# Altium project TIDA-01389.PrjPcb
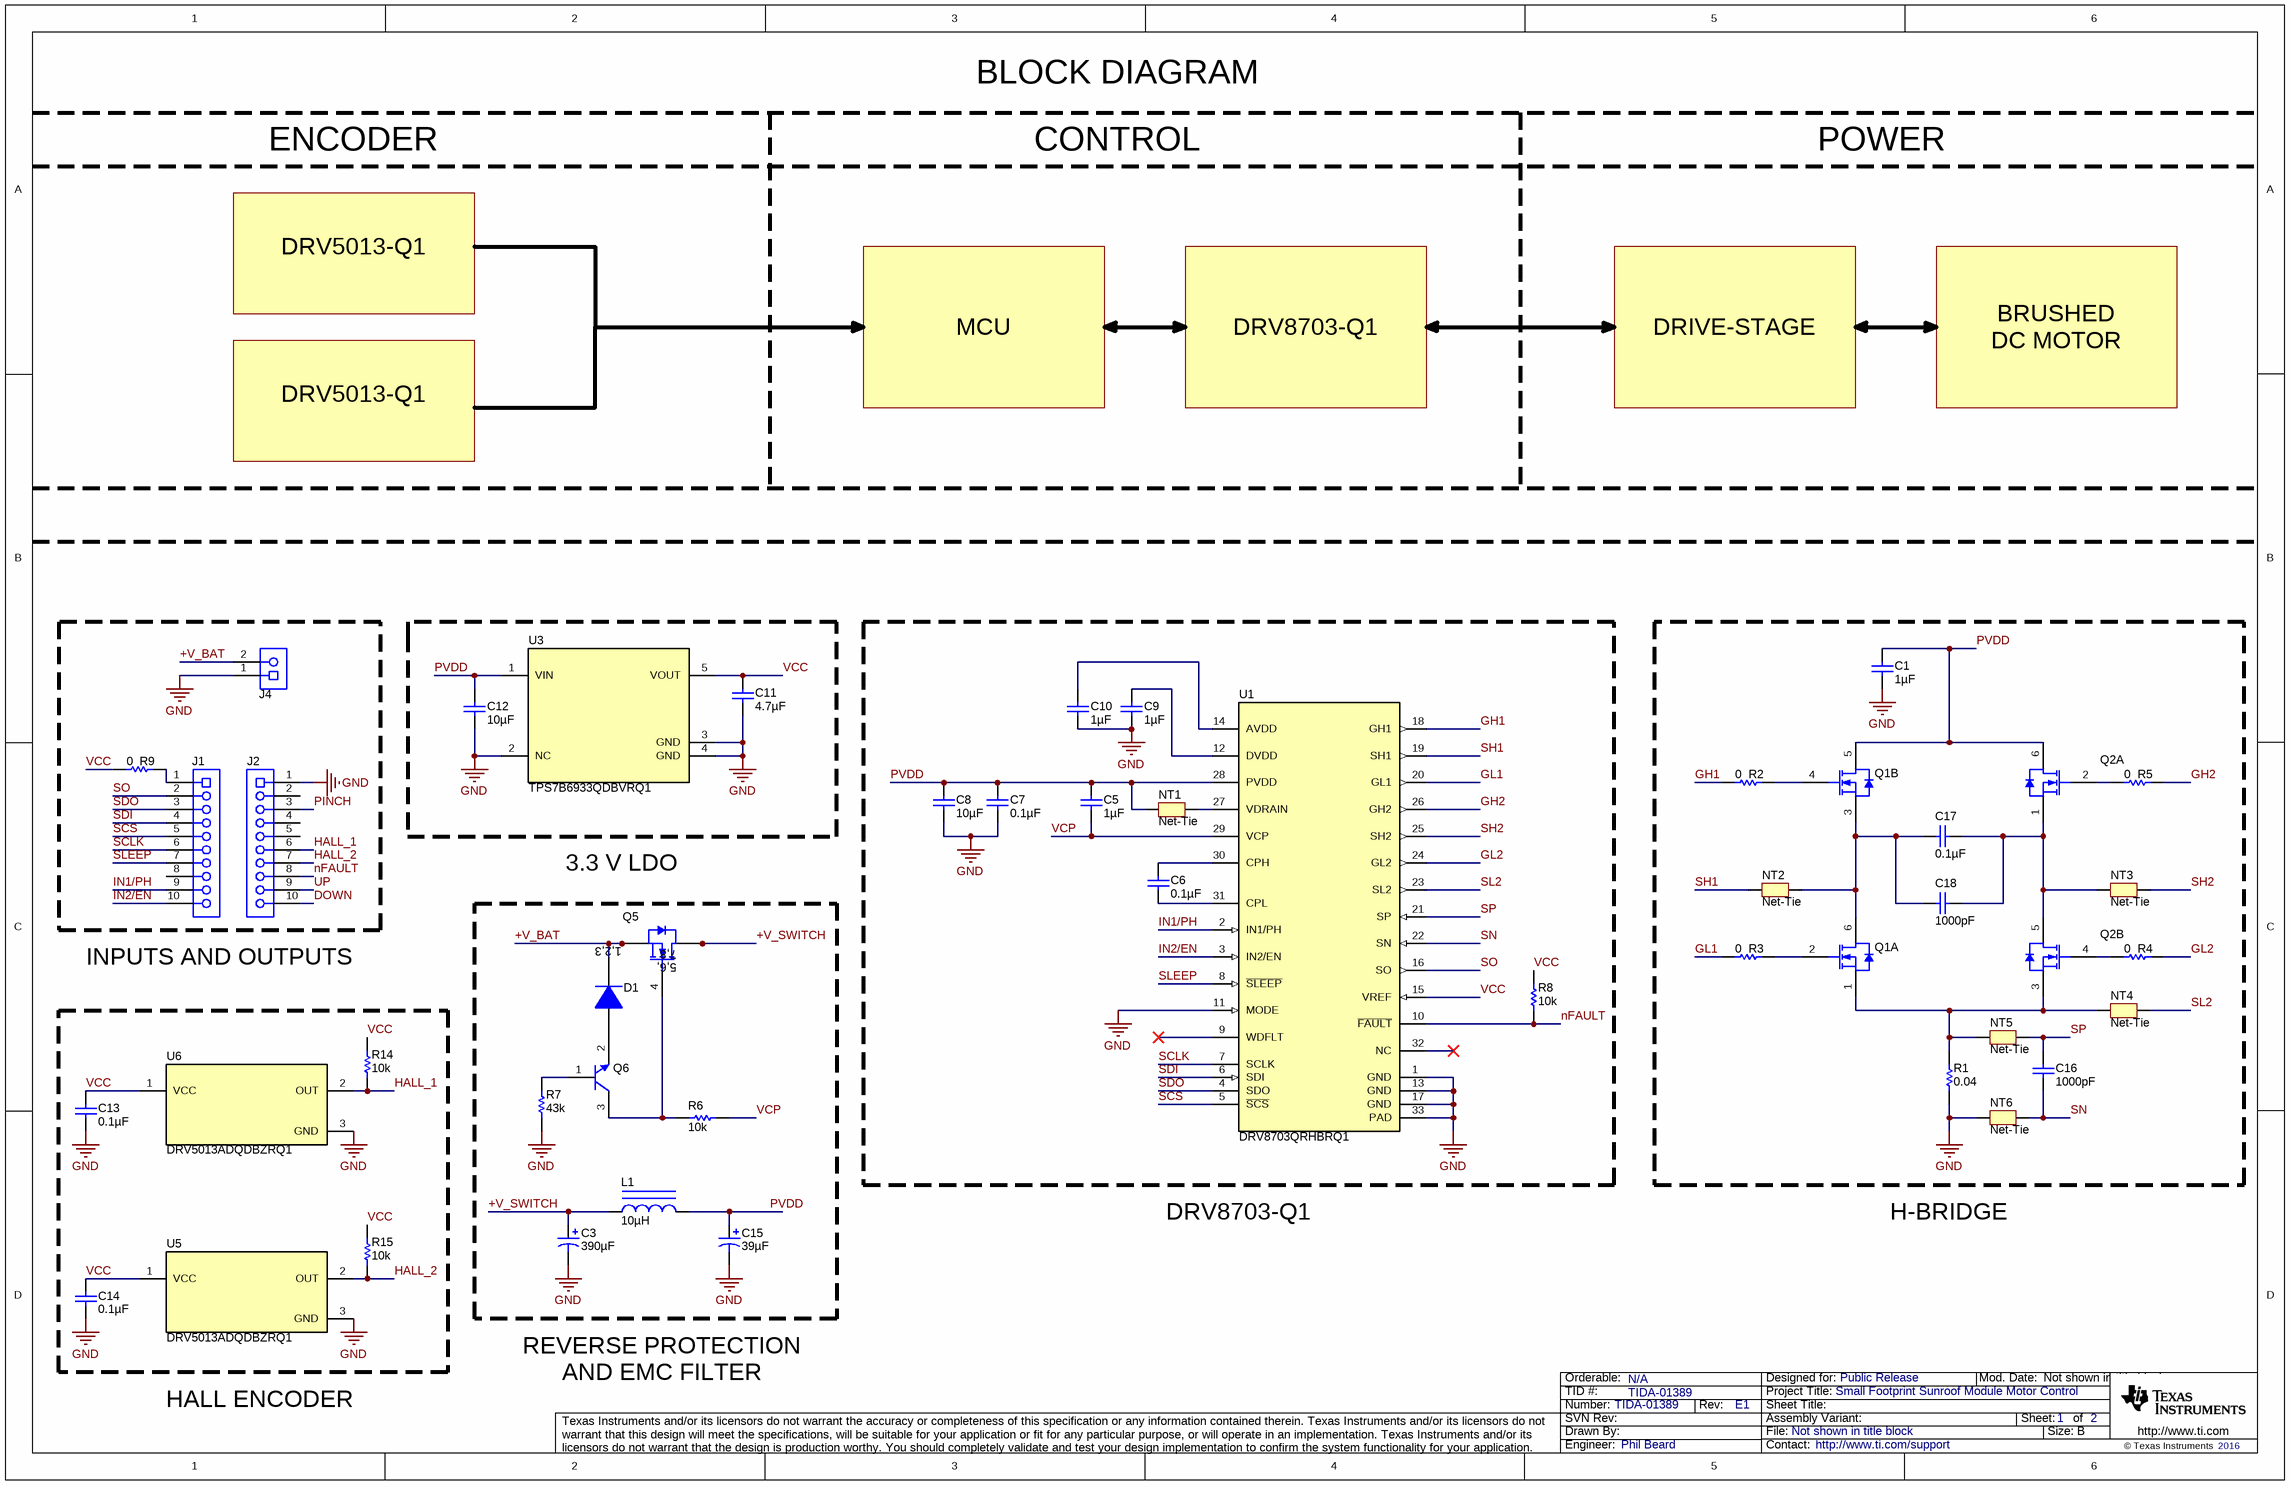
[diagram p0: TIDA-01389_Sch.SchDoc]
TID: TIDA-01389; TechSupport: http://www.ti.com/support; SCH_Rev: E1; PRJ_Title: Small Footprint Sunroof Module Motor Control; PRJ_Number: TIDA-01389; PRJ_Engineer: Phil Beard; PRJ_Customer: Public Release; PCB_Rev: E1; PCB_Layout: Phil Beard; EVM_Orderable: N/A; CopyrightYear: 2016
2 sheets, 51 parts. Net scope: global (net labels, ports and power ports of the same name join across sheets).
Board file: TIDA-01389_PCB.PcbDoc
Sheets:
  TIDA-01389_Sch.SchDoc
  TIDA-01389_Hardware.SchDoc

## Sheet TIDA-01389_Sch.SchDoc
size 431 x 279 mm; Date: Not shown in title block; ApprovedBy: Not shown in title block; CheckedBy: Not shown in title block; Author: Not shown in title block; CompanyName: Not shown in title block; Engineer: Not shown in title block; Organization: Not shown in title block; Address1: Not shown in title block; Address2: Not shown in title block; Address3: Not shown in title block; Address4: Not shown in title block; DocumentNumber: 1; Revision: Use project parameter SCH_Rev; SheetNumber: 1; SheetTotal: 2; PageSetup: Record=PageOptions¦CenterHorizontal=True¦CenterVertical=True¦PrintScale=1.00¦XCorrection=1.00¦YCorrection=1.00¦PrintKind=0¦BorderSize=5000000¦LeftOffset=0¦BottomOffset=0¦Orientation=2¦PaperLength=1000¦PaperWidth=1000¦Scale=100¦PaperSource=15¦PrintQuality=600¦MediaType=1¦DitherType=10¦PaperKind=Letter¦PrintScaleMode=1

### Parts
C1  ValueDisplayed: 1µF  [0805L]  (hidden comment: GRM21BR71H105KA12L)
C3  ValueDisplayed: 390µF  [CAPAE1030X1080]  (hidden comment: EEE-FPV391UAP)
C5  ValueDisplayed: 1µF  [0402L]  (hidden comment: C1005X5R1C105K050BC)
C6  ValueDisplayed: 0.1µF  [0402L]  (hidden comment: GCM155R71H104KE02D)
C7  ValueDisplayed: 0.1µF  [0402L]  (hidden comment: GRM155R61H104ME14D)
C8  ValueDisplayed: 10µF  [1206_180L]  (hidden comment: C3216X5R1H106K160AB)
C9  ValueDisplayed: 1µF  [0402L]  (hidden comment: GRM155R70J105MA12D)
C10  ValueDisplayed: 1µF  [0402L]  (hidden comment: GRM155R70J105MA12D)
C11  ValueDisplayed: 4.7µF  [0402L]  (hidden comment: GRM155R60J475ME47D)
C12  ValueDisplayed: 10µF  [1206_180L]  (hidden comment: C3216X5R1H106K160AB)
C13  ValueDisplayed: 0.1µF  [0402L]  (hidden comment: GRM155R61H104ME14D)
C14  ValueDisplayed: 0.1µF  [0402L]  (hidden comment: GRM155R61H104ME14D)
C15  ValueDisplayed: 39µF  [PCV_800x1200]  (hidden comment: PCV1J390MCL2GS)
C16  ValueDisplayed: 1000pF  [0402L]  (hidden comment: GRM155R71C102KA01D)
C17  ValueDisplayed: 0.1µF  [0402]  (hidden comment: GCM155R71C104KA55D)
C18  ValueDisplayed: 1000pF  [0402L]  (hidden comment: GRM155R71C102KA01D)
D1  1N4148W-TP  [SOD-123]  (value not drawn)
J1  SSQ-110-01-T-S  [Samtec_SSQ-110-01-x-S]  (value not drawn)
J2  SSQ-110-01-T-S  [Samtec_SSQ-110-01-x-S]  (value not drawn)
J4  691214310002  [Wurth_691214310002]  (value not drawn)
L1  ValueDisplayed: 10µH  [SRP1265A]  (hidden comment: SRP1265A-100M)
NT1  Net-Tie  [Net-Tie_10milWide_30milLong]  (net tie, no BOM)
NT2  Net-Tie  [Net-Tie_10milWide_30milLong]  (net tie, no BOM)
NT3  Net-Tie  [Net-Tie_10milWide_30milLong]  (net tie, no BOM)
NT4  Net-Tie  [Net-Tie_10milWide_30milLong]  (net tie, no BOM)
NT5  Net-Tie  [Net-Tie_10milWide_30milLong]  (net tie, no BOM)
NT6  Net-Tie  [Net-Tie_10milWide_30milLong]  (net tie, no BOM)
Q1  SQJ940EP-T1-GE3  [PowerPAK_SO-8L_Dual]  (value not drawn)  (parts A,B of 2)
Q2  SQJ940EP-T1-GE3  [PowerPAK_SO-8L_Dual]  (value not drawn)  (parts A,B of 2)
Q5  SQ4470EY-T1-GE3  [SOIC-8L]  (value not drawn)
Q6  MMBTA06-7-F  [SOT-23]  (value not drawn)
R1  ValueDisplayed: 0.04  [2010]  (hidden comment: CSRN2010FK40L0)
R2  value 0  [0603L]  (hidden comment: CRCW06030000Z0EA)
R3  value 0  [0603L]  (hidden comment: CRCW06030000Z0EA)
R4  value 0  [0603L]  (hidden comment: CRCW06030000Z0EA)
R5  value 0  [0603L]  (hidden comment: CRCW06030000Z0EA)
R6  ValueDisplayed: 10k  [0402L]  (hidden comment: CRCW040210K0JNED)
R7  ValueDisplayed: 43k  [0402L]  (hidden comment: CRCW040243K0JNED)
R8  ValueDisplayed: 10k  [0402L]  (hidden comment: CRCW040210K0JNED)
R9  value 0  [0603L]  (hidden comment: CRCW06030000Z0EA)
R14  ValueDisplayed: 10k  [0402L]  (hidden comment: CRCW040210K0JNED)
R15  ValueDisplayed: 10k  [0402L]  (hidden comment: CRCW040210K0JNED)
U1  DRV8703QRHBRQ1  [RHB0032E]
U3  TPS7B6933QDBVRQ1  [DBV0005A_N]
U5  DRV5013ADQDBZRQ1  [DBZ0003A_N]
U6  DRV5013ADQDBZRQ1  [DBZ0003A_N]

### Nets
GND: C1.2 C3.2(-) C7.2 C8.2 C9.2 C10.2 C11.2 C12.2 C13.2 C14.2 C15.2(-) J2.1 J4.1 NT6.1 R1.1 R7.1 U1.1(GND) U1.11(MODE) U1.13(GND) U1.17(GND) U1.33(PAD) U3.2(NC) U3.3(GND) U3.4(GND) U5.3(GND) U6.3(GND)
+V_BAT: D1.1(K) J4.2 Q5.1(S) Q5.2(S) Q5.3(S)
+V_SWITCH: C3.1(+) L1.1 Q5.5(D) Q5.6(D) Q5.7(D) Q5.8(D)
DOWN: J2.10
GH1: R2.2 U1.18(GH1)
GH2: R5.1 U1.26(GH2)
GL1: R3.2 U1.20(GL1)
GL2: R4.1 U1.24(GL2)
HALL_1: J2.6 R14.1 U6.2(OUT)
HALL_2: J2.7 R15.1 U5.2(OUT)
IN1/PH: J1.9 U1.2(IN1/PH)
IN2/EN: J1.10 U1.3(IN2/EN)
nFAULT: J2.8 R8.1 U1.10(~{FAULT})
PINCH: J2.3
PVDD: C1.1 C5.1 C7.1 C8.1 C12.1 C15.1(+) L1.2 NT1.1 Q1.5(D2) Q2.6(D1) U1.28(PVDD) U3.1(VIN)
SCLK: J1.6 U1.7(SCLK)
SCS: J1.5 U1.5(~{SCS})
SDI: J1.4 U1.6(SDI)
SDO: J1.3 U1.4(SDO)
SH1: NT2.1 U1.19(SH1)
SH2: NT3.2 U1.25(SH2)
SL2: NT4.2 U1.23(SL2)
SLEEP: J1.7 U1.8(~{SLEEP})
SN: C16.2 NT6.2 U1.22(SN)
SO: J1.2 U1.16(SO)
SP: C16.1 NT5.2 U1.21(SP)
UP: J2.9
VCC: C11.1 C13.1 C14.1 R8.2 R9.2 R14.2 R15.2 U1.15(VREF) U3.5(VOUT) U5.1(VCC) U6.1(VCC)
VCP: C5.2 R6.2 U1.29(VCP)
NetC6_1: C6.1 U1.31(CPL)
NetC6_2: C6.2 U1.30(CPH)
NetC9_1: C9.1 U1.12(DVDD)
NetC10_1: C10.1 U1.14(AVDD)
NetC17_1: C17.1 C18.1 NT2.2 Q1.3(S2) Q1.6(D1)
NetC17_2: C17.2 C18.2 NT3.1 Q2.1(S1) Q2.5(D2)
NetD1_2: D1.2(A) Q6.2(E)
NetJ1_1: J1.1 R9.1
NetNT1_2: NT1.2 U1.27(VDRAIN)
NetNT4_1: NT4.1 NT5.1 Q1.1(S1) Q2.3(S2) R1.2
NetQ1_2: Q1.2(G1) R3.1
NetQ1_4: Q1.4(G2) R2.1
NetQ2_2: Q2.2(G1) R5.2
NetQ2_4: Q2.4(G2) R4.2
NetQ5_4: Q5.4(G) Q6.3(C) R6.1
NetQ6_1: Q6.1(B) R7.2

Not connected (* = marked no-connect by the designer): J1 8; J2 2 4 5; U1 9(WDFLT)* 32(NC)*

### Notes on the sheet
- BLOCK DIAGRAM
- ENCODER
- CONTROL
- POWER
- DRV5013-Q1
- MCU
- DRV8703-Q1
- DRIVE-STAGE
- BRUSHED
- DC MOTOR
- 3.3 V LDO
- INPUTS AND OUTPUTS
- H-BRIDGE
- REVERSE PROTECTION
- AND EMC FILTER
- HALL ENCODER

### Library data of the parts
C1 = GRM21BR71H105KA12L: CAP, CERM, 1 µF, 50 V, +/- 10%, X7R, 0805; Manufacturer: MuRata; Polarized: N; CompType: Capacitor; Value: 1uF; U/M: EA; Cap_F: 0.000001; Tolerance_%: 10; Value1: Unknown; VDC_V: 50; Value2: 50V; TaMin_C: -55; TaMax_C: 125; Cap_Case: 0805; AEC Category: Q200
C3 = EEE-FPV391UAP: CAP, AL, 390 µF, 35 V, +/- 20%, 0.08 ohm, AEC-Q200 Grade 2, SMD; Manufacturer: Panasonic; Polarized: Y; CompType: Capacitor; Value: 390uF; U/M: EA; Cap_F: 0.00039; Tolerance_%: 20; VDC_V: 35; Value2: 35V; ESR_ohm: 0.08; IRMS_A: 0.85; TaMin_C: -55; TaMax_C: 105; Cap_Case: 10x10.2mm; AEC Category: Q200; AEC Grade: 2
C5 = C1005X5R1C105K050BC: CAP, CERM, 1 µF, 16 V, +/- 10%, X5R, 0402; Manufacturer: TDK; Polarized: N; CompType: Capacitor; Value: 1uF; U/M: EA; Cap_F: 0.000001; Tolerance_%: 10; Value1: Unknown; VDC_V: 16; Value2: 16V; TaMin_C: -55; TaMax_C: 85; Cap_Case: 0402; SizeArea_mm2: 0.5; SizeAreaWB_mm2: 3; SizeX_mm: 1; SizeZ_mm: 0.6; AEC Category: Q200
C6 = GCM155R71H104KE02D: CAP, CERM, 0.1 µF, 50 V, +/- 10%, X7R, AEC-Q200 Grade 1, 0402; Manufacturer: MuRata; Polarized: N; CompType: Capacitor; Value: 0.1uF; U/M: EA; Cap_F: 0.0000001; Tolerance_%: 10; Value1: Unknown; VDC_V: 50; Value2: 50V; TaMin_C: -55; TaMax_C: 125; Cap_Case: 0402; SizeArea_mm2: 0.5; SizeAreaWB_mm2: 3; SizeX_mm: 1; SizeZ_mm: 0.6; AEC Category: Q200; AEC Qualified: Y
C7 C13 C14 = GRM155R61H104ME14D: CAP, CERM, 0.1 µF, 50 V, +/- 20%, X5R, 0402; Manufacturer: MuRata; Polarized: N; CompType: Capacitor; Value: 0.1uF; U/M: EA; Cap_F: 0.0000001; Tolerance_%: 20; Value1: Unknown; VDC_V: 50; Value2: 50V; TaMin_C: -55; TaMax_C: 85; Cap_Case: 0402; SizeArea_mm2: 0.5; SizeAreaWB_mm2: 3; SizeX_mm: 1; SizeZ_mm: 0.6; AEC Category: Q200
C8 C12 = C3216X5R1H106K160AB: CAP, CERM, 10 µF, 50 V, +/- 10%, X5R, 1206; Manufacturer: TDK; Polarized: N; CompType: Capacitor; Value: 10uF; U/M: EA; Cap_F: 0.00001; Tolerance_%: 10; ESR_ohm: 0.002229; Value1: 0.002229 ohm; VDC_V: 50; Value2: 50V; IRMS_A: 4.85932; TaMin_C: -55; TaMax_C: 85; Cap_Case: 1206_180; SizeArea_mm2: 5.12; SizeAreaWB_mm2: 10.92; SizeX_mm: 3.2; SizeY_mm: 1.6; SizeZ_mm: 1.8; AEC Category: Q200
C9 C10 = GRM155R70J105MA12D: CAP, CERM, 1 µF, 6.3 V, +/- 20%, X7R, 0402; Manufacturer: MuRata; Polarized: N; CompType: Capacitor; Value: 1uF; U/M: EA; Cap_F: 0.000001; Tolerance_%: 20; Value1: Unknown; VDC_V: 6.3; Value2: 6.3V; TaMin_C: -55; TaMax_C: 125; Cap_Case: 0402; SizeArea_mm2: 0.5; SizeAreaWB_mm2: 3; SizeX_mm: 1; SizeZ_mm: 0.6; AEC Category: Q200
C11 = GRM155R60J475ME47D: CAP, CERM, 4.7 µF, 6.3 V, +/- 20%, X5R, 0402; Manufacturer: MuRata; Polarized: N; CompType: Capacitor; Value: 4.7uF; U/M: EA; Cap_F: 0.0000047; Tolerance_%: 20; Value1: Unknown; VDC_V: 6.3; Value2: 6.3V; TaMin_C: -55; TaMax_C: 85; Cap_Case: 0402; SizeArea_mm2: 0.5; SizeAreaWB_mm2: 3; SizeX_mm: 1; SizeZ_mm: 0.6; AEC Category: Q200
C15 = PCV1J390MCL2GS: CAP, Aluminum Polymer, 39 µF, 63 V, +/- 20%, 0.029 ohm, AEC-Q200 Grade 2, D8xL12mm SMD; Manufacturer: Nichicon; Polarized: Y; CompType: Capacitor; Value: 39uF; U/M: EA; Cap_F: 0.000039; Tolerance_%: 20; VDC_V: 63; Value2: 63V; ESR_ohm: 0.029; IRMS_A: 3.4; TaMin_C: -55; TaMax_C: 105; Cap_Case: 8x12mm; AEC Category: Q200; AEC Grade: 2
C16 C18 = GRM155R71C102KA01D: CAP, CERM, 1000 pF, 16 V, +/- 10%, X7R, 0402; Manufacturer: MuRata; Polarized: N; CompType: Capacitor; Value: 1000pF; U/M: EA; Cap_F: 0.000000001; Tolerance_%: 10; Value1: Unknown; VDC_V: 16; Value2: 16V; TaMin_C: -55; TaMax_C: 125; Cap_Case: 0402; AEC Category: Q200
C17 = GCM155R71C104KA55D: CAP, CERM, 0.1 µF, 16 V, +/- 10%, X7R, 0402; Manufacturer: MuRata; Polarized: N; CompType: Capacitor; Value: 0.1uF; U/M: EA; Cap_F: 0.0000001; Tolerance_%: 10; Value1: Unknown; VDC_V: 16; Value2: 16V; TaMin_C: -55; TaMax_C: 125; AEC Category: Q200; SizeArea_mm2: 0.5; SizeAreaWB_mm2: 3; SizeX_mm: 1; SizeZ_mm: 0.6
D1 = 1N4148W-TP: Diode, Switching, 100 V, 0.15 A, SOD-123; Manufacturer: Micro Commercial Components; U/M: EA; Vf_V: 1.25; Value: 100V; Value1: 0.15A; Value2: 1.25V; Io_A: 0.15; Vr_V: 100; TJmax_C: 150; SizeAreaWB_mm2: 13.095; SizeArea_mm2: 6.545; SizeX_mm: 3.85; SizeY_mm: 1.7; SizeZ_mm: 1.35; AEC Category: Q101
J1 J2 = SSQ-110-01-T-S: Receptacle, 2.54mm, 10x1, Tin, TH; Manufacturer: Samtec; SymbolCreator: a0411947; Pitch_mm: 2.54; Gender: Female; Row_Count: 1; Current_A: 6.3; Voltage_V: 550; Cert_CSA: Y
J4 = 691214310002: Terminal Block, 2x1, 3.81mm, 24-16 AWG, 10A, 300VAC, TH; Manufacturer: Wurth Elektronik; SymbolCreator: a0412235
L1 = SRP1265A-100M: Inductor, Shielded, 10 µH, 10 A, 0.0132 ohm, AEC-Q200 Grade 0, SMD; Manufacturer: Bourns; Value: 10uH; Ind_H: 10.0E-6; Imax_A: 10; Irms: 10A @ 40C rise; Isat: 15.5A @ 20% inductance drop; DCR_ohm: 0.0132; Value2: 10A; AEC Category: Q200; AEC Qualified: Y; AEC Grade: 0
NT1-NT6 = Net-Tie: Single point connection between nets.; SymbolCreator: codlsc
Q1 Q2 = SQJ940EP-T1-GE3: MOSFET, N-CH, 40 V, 15 A, AEC-Q101, PowerPAK SO-8 Dual Asymmetric; Manufacturer: Vishay-Siliconix; Alternate Manufacturer: None; SymbolCreator: Altium; U/M: EA; ChType: N; Value: 40V; VdsMax_V: 40; Value1: 0.0188 ohm; Rdson45_ohm: 0.0188; Value2: 13.5 nC; QgTyp_nC: 13.5; Vgs_V: 20; IdsMax_A: 15; AEC Category: Q101; AEC Qualified: Y
Q5 = SQ4470EY-T1-GE3: MOSFET, N-CH, 60 V, 16 A, SOIC-8; Manufacturer: Vishay-Siliconix; Alternate Manufacturer: None; U/M: EA; ChType: N; Value: 60V; VdsMax_V: 60; Value1: ? ohm; Value2: 45 nC; QgTyp_nC: 45; Vgs_V: 20; IdsMax_A: 16; SizeAreaWB_mm2: 55.131; SizeArea_mm2: 29.351; SizeX_mm: 5.99; SizeY_mm: 4.9; SizeZ_mm: 1.75; AEC Category: Q101
Q6 = MMBTA06-7-F, Diodes Inc.: Transistor, NPN, 80 V, 0.5 A, SOT-23; CompType: BJT; PNP: 0; NPN: 1; Vceo_V: 80; Vcesat1_V: 0.25; Value: 80 V; IcRated_A: 0.5; Value1: 0.5 A; TaMin_C: -55; TaMax_C: 150; U/M: EA; AEC Category: Q101
R1 = CSRN2010FK40L0: RES, 0.04, 1%, 1 W, 2010; Manufacturer: Stackpole Electronics Inc; CompType: Resistor; Value: 0.04; Value_Code: R040; Tolerance_%: 1; Value2: 1W; TempCo: 250 ppm/C; U/M: EA; AEC Category: Q200
R2-R5 R9 = CRCW06030000Z0EA: RES, 0, 5%, 0.1 W, 0603; Manufacturer: Vishay-Dale; CompType: Resistor; Value_Code: 0000; Tolerance_%: 5; Power_W: 0.1; Value2: 0.1W; VDC_V: 75; TempCo: 200 ppm/C; EIA_Code: E24; U/M: EA; AEC Category: Q200
R6 R8 R14 R15 = CRCW040210K0JNED: RES, 10 k, 5%, 0.063 W, 0402; Manufacturer: Vishay-Dale; CompType: Resistor; Value: 10k; Res_ohm: 10000; Value_Code: 10k0; Tolerance_%: 5; Power_W: 0.063; Value2: 0.063W; VDC_V: 50; TempCo: 200 ppm/C; SizeArea_mm2: 0.5; SizeX_mm: 1; SizeZ_mm: 0.6; EIA_Code: E24; U/M: EA; AEC Category: Q200
R7 = CRCW040243K0JNED: RES, 43 k, 5%, 0.063 W, 0402; Manufacturer: Vishay-Dale; CompType: Resistor; Value: 43k; Res_ohm: 43000; Value_Code: 43k0; Tolerance_%: 5; Power_W: 0.063; Value2: 0.063W; VDC_V: 50; TempCo: 200 ppm/C; SizeArea_mm2: 0.5; SizeX_mm: 1; SizeZ_mm: 0.6; EIA_Code: E24; U/M: EA; AEC Category: Q200
U1 = DRV8703QRHBRQ1: Full-Bridge Automotive Gate Driver, RHB0032E; Alternate PartNumber: DRV8703QRHBTQ1; Manufacturer: Texas Instruments; SymbolCreator: Altium; SizeArea_mm2: 25; SizeAreaWB_mm2: 49; SizeX_mm: 5; SizeZ_mm: 1; CompType: IC; U/M: EA
U3 = TPS7B6933QDBVRQ1: High Voltage Ultra Low Iq - Low Drop Out Regulator, DBV0005A; Manufacturer: Texas Instruments; SymbolCreator: Altium; SizeArea_mm2: 8.12; SizeAreaWB_mm2: 14.82; SizeX_mm: 2.8; SizeY_mm: 2.9; SizeZ_mm: 1.45; CompType: IC; U/M: EA
U5 U6 = DRV5013ADQDBZRQ1: Automotive Digital-Latch Hall Effect Sensor, DBZ0003A; Alternate PartNumber: DRV5013ADQDBZTQ1; Manufacturer: Texas Instruments; SymbolCreator: Altium; SizeArea_mm2: 7.5; SizeAreaWB_mm2: 14; SizeX_mm: 2.5; SizeY_mm: 3; SizeZ_mm: 1.12; CompType: IC; U/M: EA

## Sheet TIDA-01389_Hardware.SchDoc
size 431 x 279 mm; Date: Not shown in title block; ApprovedBy: Not shown in title block; CheckedBy: Not shown in title block; Author: Not shown in title block; CompanyName: Not shown in title block; Engineer: Not shown in title block; Organization: Not shown in title block; Address1: Not shown in title block; Address2: Not shown in title block; Address3: Not shown in title block; Address4: Not shown in title block; DocumentNumber: 1; Revision: Use project parameter SCH_Rev; SheetNumber: 2; SheetTotal: 2; PageSetup: Record=PageOptions¦CenterHorizontal=True¦CenterVertical=True¦PrintScale=1.00¦XCorrection=1.00¦YCorrection=1.00¦PrintKind=0¦BorderSize=5000000¦LeftOffset=0¦BottomOffset=0¦Orientation=2¦PaperLength=1000¦PaperWidth=1000¦Scale=100¦PaperSource=15¦PrintQuality=600¦MediaType=1¦DitherType=10¦PaperKind=Letter¦PrintScaleMode=1
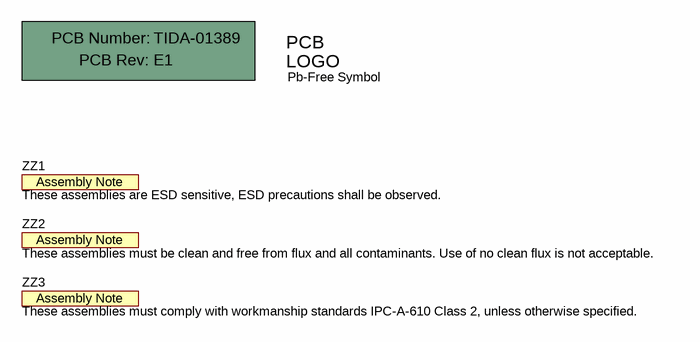
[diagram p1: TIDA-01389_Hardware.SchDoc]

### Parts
!PCB  Printed Circuit Board  (value not drawn)  (mechanical)
Logo2  Pb-Free Symbol  [Pb-Free_Overlay_Small]  (no BOM)
ZZ1  These assemblies are ESD sensitive, ESD precautions shall be observed.  [AssemblyNote]  (no BOM)
ZZ2  These assemblies must be clean and free from flux and all contaminants. Use of no clean flux is not acceptable.  [AssemblyNote]  (no BOM)
ZZ3  These assemblies must comply with workmanship standards IPC-A-610 Class 2, unless otherwise specified.  [AssemblyNote]  (no BOM)

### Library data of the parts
!PCB = PCB: Manufacturer: Any; PartNumber: TIDA-01389; SymbolCreator: a0412235
Logo2 = Pb-Free: SymbolCreator: a0412235
ZZ1-ZZ3 = AssemblyNote: SymbolCreator: codlsc

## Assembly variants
001: not fitted C17 C18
